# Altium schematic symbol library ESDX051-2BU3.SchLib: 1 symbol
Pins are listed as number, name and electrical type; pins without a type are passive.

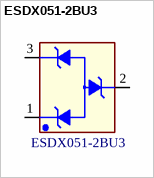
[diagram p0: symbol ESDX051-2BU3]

## ESDX051-2BU3
designator D?
footprint ST_ST0201_optD
pins: 1 K1, 2 K2, 3 K3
